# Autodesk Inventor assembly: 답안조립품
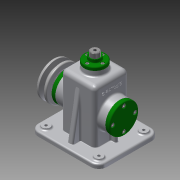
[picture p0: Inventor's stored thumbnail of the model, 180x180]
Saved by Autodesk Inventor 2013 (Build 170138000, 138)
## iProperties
Created: 2016-01
Part Number: 답안조립품
Document SubType Name: Assembly
Designer: Administrator
Author: Administrator
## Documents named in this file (19)
- C:\Users\Administrator\Desktop\460127V1006\답안조립품.iam
- C:\Users\Administrator\Desktop\460127V1006\1.본체.ipt
- C:\Users\Administrator\Desktop\460127V1006\V-벨트풀리.ipt
- C:\Users\Administrator\Desktop\460127V1006\고정핀.ipt
- C:\Users\Administrator\Desktop\460127V1006\뒤커버.ipt
- C:\Users\Administrator\Desktop\460127V1006\링크.ipt
- C:\Users\Administrator\Desktop\460127V1006\멈춤링 6 x 5.ipt
- C:\Users\Administrator\Desktop\460127V1006\멈춤링 15 x 1.ipt
- C:\Users\Administrator\Desktop\460127V1006\베어링 15 x 35 x 11.ipt
- C:\Users\Administrator\Desktop\460127V1006\볼트 M3 x 8.ipt
- C:\Users\Administrator\Desktop\460127V1006\볼트 M4 x 10.ipt
- C:\Users\Administrator\Desktop\460127V1006\볼트 M6 x 12.ipt
- C:\Users\Administrator\Desktop\460127V1006\상부부시.ipt
- C:\Users\Administrator\Desktop\460127V1006\슬라이드바.ipt
- C:\Users\Administrator\Desktop\460127V1006\앞커버.ipt
- C:\Users\Administrator\Desktop\460127V1006\오일실 15 25 7.ipt
- C:\Users\Administrator\Desktop\460127V1006\와셔.ipt
- C:\Users\Administrator\Desktop\460127V1006\키 5 x 5 x 14.ipt
- C:\Users\Administrator\Desktop\460127V1006\편심축.ipt
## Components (16 placed, 6 different names)
1. 1.본체:1
2. V-벨트풀리:1 — 각도:2
3. 고정핀:1
4. ISO 4018 M6 x 12:1
5. ISO 4762 M4 x 10:1
6. ISO 4762 M4 x 10:2
7. ISO 4762 M4 x 10:3
8. ISO 4762 M4 x 10:4
9. ISO 4762 M4 x 10:5
10. ISO 4762 M4 x 10:6
11. ISO 4762 M4 x 10:7
12. ISO 4762 M4 x 10:8
13. ISO 4762 M3 x 8:1
14. ISO 4762 M3 x 8:2
15. ISO 4762 M3 x 8:3
16. ISO 4762 M3 x 8:4
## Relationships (1: Angle 1)
- 각도:2 [Angle]: V-벨트풀리:1
